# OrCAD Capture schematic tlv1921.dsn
size A
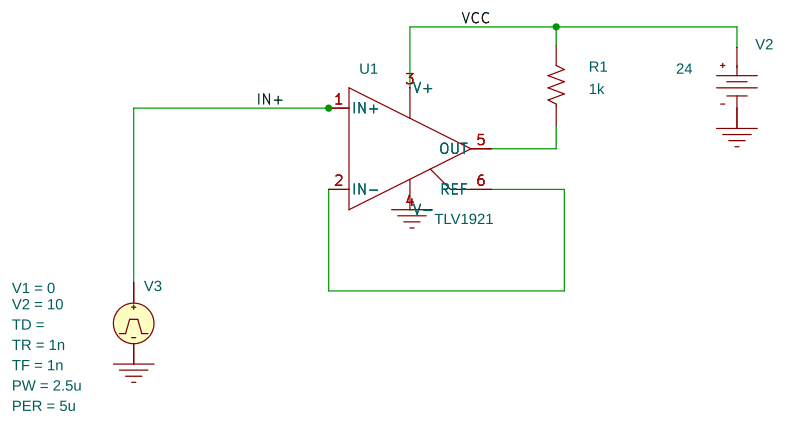
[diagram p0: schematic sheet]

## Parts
R1  1k  [AXRC05]
U1  TLV1921
V2  VDC
V3  VPULSE

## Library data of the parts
R1 = R
U1 = TLV1921_1
V2 = VDC: DC: 24
V3 = VPULSE: PER: 5u; PW: 2.5u; TF: 1n; TR: 1n; V1: 0; V2: 10

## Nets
VCC: R1.2 U1.3(V+) V2.0(+)
0: U1.4(V-) V2.1(-) V3.2(-)
IN+: U1.1(IN+) V3.1(+)
N00194: R1.1 U1.5(OUT)
N00233: U1.2(IN-) U1.6(REF)
